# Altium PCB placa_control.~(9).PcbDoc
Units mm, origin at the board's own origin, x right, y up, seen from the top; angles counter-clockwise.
Board outline 152.4 x 101.6 mm, 2 copper layers (Top Layer, Bottom Layer); 35 components, 26 nets, 134 pads, 100 vias.
Unrouted connection lines stored in the file: 44.
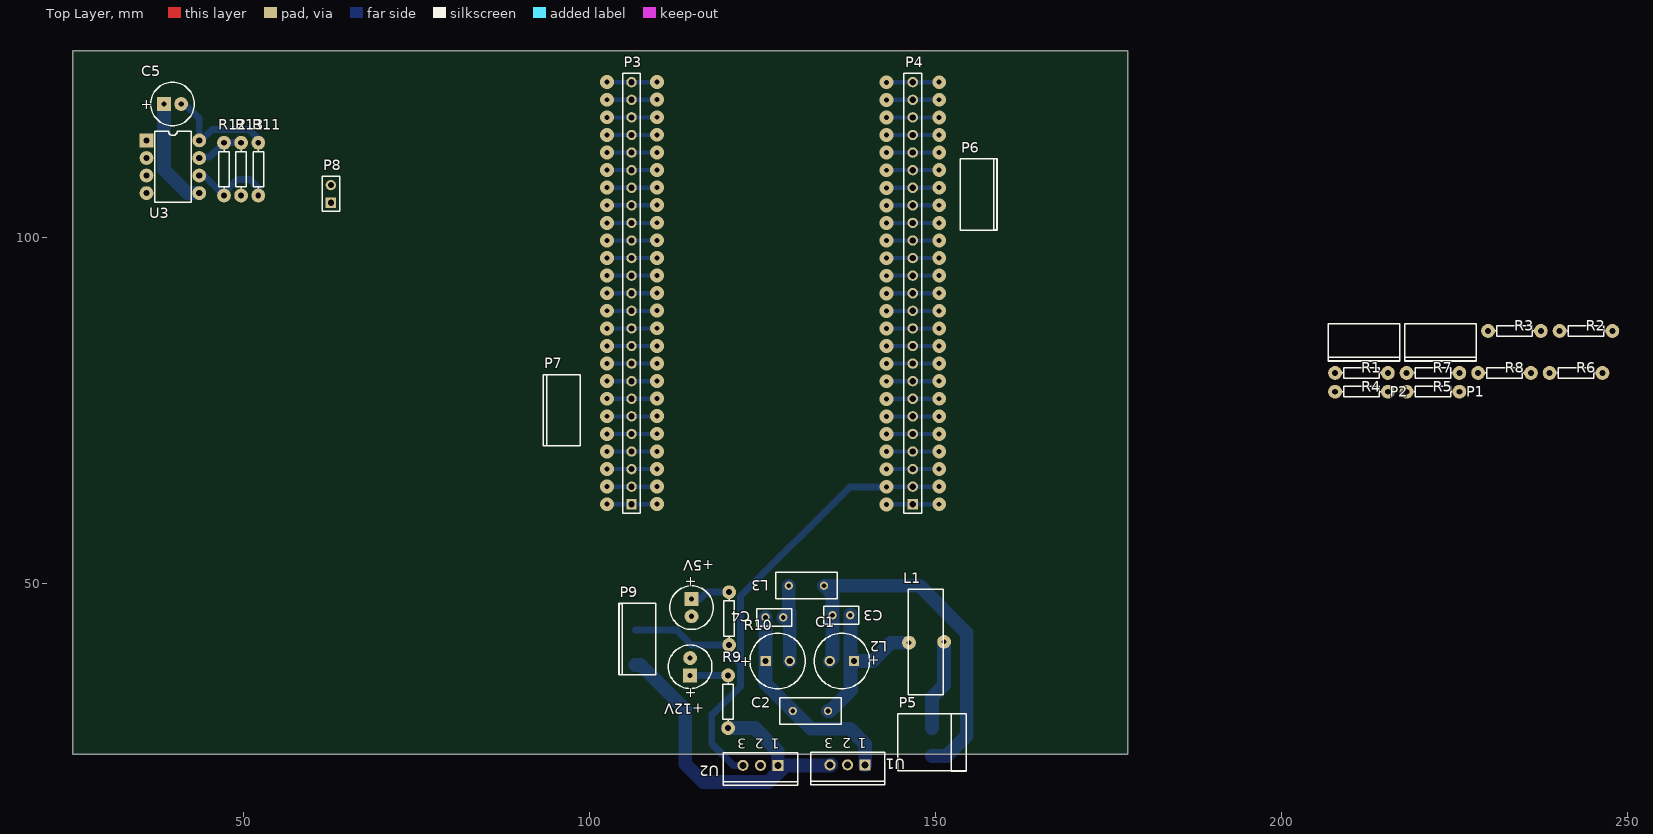
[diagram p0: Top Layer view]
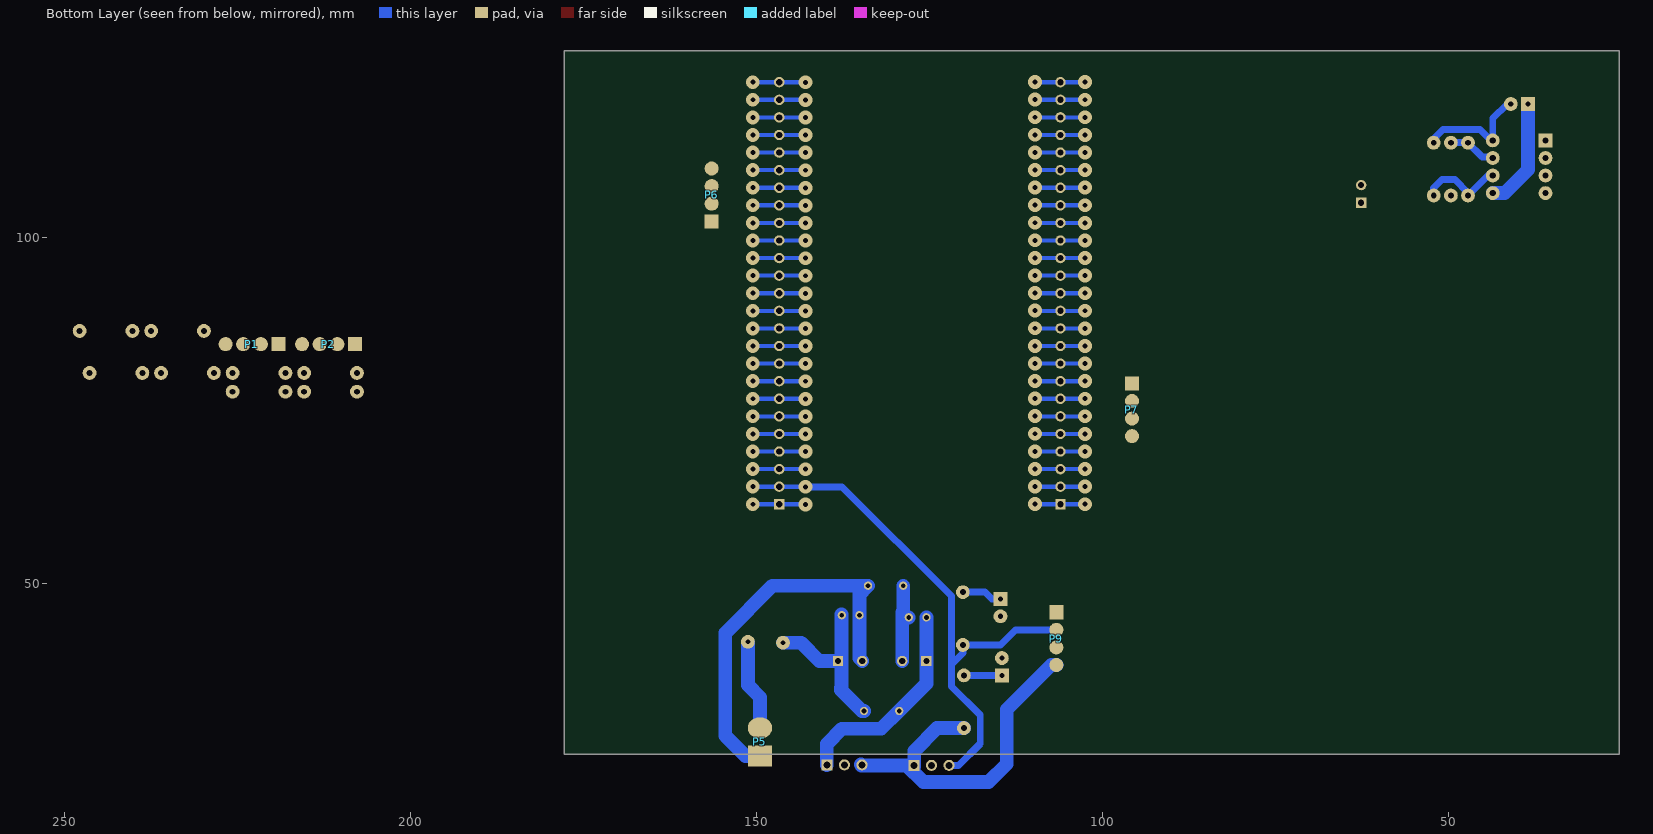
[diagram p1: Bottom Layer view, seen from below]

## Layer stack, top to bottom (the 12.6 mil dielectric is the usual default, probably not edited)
Top Layer: signal copper 0.0356
Dielectric: dielectric 0.32, FR-4, Dk 4.8
Bottom Layer: signal copper 0.0356

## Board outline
25.4,25.4 177.8,25.4 177.8,127 25.4,127

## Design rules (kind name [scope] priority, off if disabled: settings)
Clearance [All] p1: gap=0.254
ComponentClearance [All] p1: gap=0.254 collisioncheckmode=3 verticalgap=0.254
PolygonConnect [All] p1: connectstyle=Relief reliefconductorwidth=0.254 reliefentries=4 polygonreliefangle="90 Angle"
RoomDefinition REGULADOR [InComponentClass('REGULADOR')] p1: confinementstyle=ConfineIn formatcopy=TRUE lockcomponents=FALSE outline 98.375,17.575 155.697,17.575 155.697,54.2 98.375,54.2
RoomDefinition INTERFAZ [InComponentClass('INTERFAZ')] p2: confinementstyle=ConfineIn formatcopy=TRUE lockcomponents=FALSE outline 15.525,100.025 66.325,100.025 66.325,125.425 15.525,125.425
RoomDefinition ENCODER [InComponentClass('ENCODER')] p3: confinementstyle=ConfineIn formatcopy=TRUE lockcomponents=FALSE outline 206.375,62.738 257.175,62.738 257.175,88.138 206.375,88.138
RoomDefinition BOARD-ARM [InComponentClass('BOARD-ARM')] p4: confinementstyle=ConfineOut formatcopy=TRUE lockcomponents=FALSE outline 166.025,120.7 232.827,120.7 232.827,146.1 166.025,146.1
RoomDefinition placa_control_esquema [InComponentClass('placa_control_esquema')] p5: confinementstyle=ConfineIn formatcopy=TRUE lockcomponents=FALSE outline 129.325,143.075 180.125,143.075 180.125,168.475 129.325,168.475
RoutingVias [All] p1: holewidth=0.711 width=2 viastyle="Through Hole" minholewidth=0.711 minwidth=1.27 maxholewidth=0.711 maxwidth=2
SolderMaskExpansion [All] p1: expansion=0.102
TestPointUsage [All] p1: valid=0 allowmultiple=FALSE
Testpoint [All] p1: side=15 testpointundercomponent=TRUE minsize=1.016 maxsize=2.54 preferedsize=1.524 minholesize=0 maxholesize=1.016 preferedholesize=0.813 testpointgrid=0.025 style=1023 order=0123456789
Width [All] p1: maxlimit=2 minlimit=0.6 preferedwidth=0.8
18 further rules are at their usual default settings.

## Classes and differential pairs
component class placa_control_esquema: P6 P7 P9
component class REGULADOR: +5V +12V C1 C2 C3 C4 L1 L2 L3 P5 R9 R10 U1 U2
component class BOARD-ARM: P3 P4
component class ENCODER: P1 P2 R1 R2 R3 R4 R5 R6 R7 R8
component class INTERFAZ: C5 P8 R11 R12 R13 U3

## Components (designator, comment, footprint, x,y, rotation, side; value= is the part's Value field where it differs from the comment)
+5V "LED2" CAPPR2.5-6.3X5 114.783,46.558 r270 top (schematic designator VCC2)
+12V "LED2" CAPPR2.5-6.3X5 114.579,38.024 r90 top (schematic designator VCC1)
C1 "Cap Pol3" CAPPR3.5-8X15 136.495,38.855 r180 top
C2 "Cap Pol3" CAPPR3.5-8X15 127.224,38.855 r0 top
C3 "Cap" RAD-0.1 136.424,45.464 r0 top
C4 "Cap" RAD-0.1 126.747,45.159 r180 top
C5 "Cap" CAPPR2.5-6.3X5 39.819,119.308 r0 top
L1 "Inductor Iron" bobina_Choque 151.137,39.085 r90 top
L2 "Inductor" RAD-0.2 131.949,31.641 r180 top
L3 "Inductor" RAD-0.2 131.369,49.731 r180 top
P1 "Header 4" HDR1X5 226.695,76.989 r0 top
P2 "Header 4" HDR1X5 215.646,76.989 r0 top
P3 "Header 25" HDR1X25 106.115,61.49 r90 top
P4 "Header 25" HDR1X25 146.73,61.49 r90 top
P5 "Header 2" pwheader1x2 149.514,27.285 r90 top
P6 "Header 4" HDR1X5 164.109,109.982 r90 top
P7 "Header 4" HDR1X5 88.163,71.323 r270 top
P8 "Header 2" HDR1X2 62.687,105.054 r90 top
P9 "Header 4" HDR1X5 99.085,38.278 r270 top
R1 "metal film 2%" AXIAL-0.3 211.541,80.459 r0 top
R2 "metal film 2%" AXIAL-0.3 243.97,86.528 r0 top
R3 "metal film 2%" AXIAL-0.3 233.639,86.528 r0 top
R4 "metal film 2%" AXIAL-0.3 211.541,77.748 r0 top
R5 "metal film 2%" AXIAL-0.3 221.872,77.748 r0 top
R6 "metal film 2%" AXIAL-0.3 242.534,80.459 r0 top
R7 "metal film 2%" AXIAL-0.3 221.872,80.459 r0 top
R8 "metal film 2%" AXIAL-0.3 232.203,80.459 r0 top
R9 "Carbon 1/8w 5%" AXIAL-0.3 120.066,32.969 r270 top
R10 "Carbon 1/8w 5%" AXIAL-0.3 120.218,44.983 r270 top
R11 "Carbon 1/8w 5%" AXIAL-0.3 52.204,109.9 r90 top
R12 "Carbon 1/8w 5%" AXIAL-0.3 47.251,109.9 r270 top
R13 "Carbon 1/8w 5%" AXIAL-0.3 49.728,109.9 r90 top
U1 "LM78L12ACZ" T03B 137.32,23.851 r180 top
U2 "LM78L05ACZ" T03B 124.738,23.785 r180 top
U3 "SN75176BP" 626-05 39.869,110.24 r270 top

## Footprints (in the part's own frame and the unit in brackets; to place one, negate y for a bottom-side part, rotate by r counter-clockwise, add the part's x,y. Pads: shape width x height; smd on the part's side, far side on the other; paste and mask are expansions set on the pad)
626-05 [mm] "DIP; 8 Leads; Row Spacing 7.62 mm; Pitch 2.54 mm"
  rect 2x2 hole 0.9: 1(-3.81,-3.81)
  round 2 hole 0.9: 2(-1.27,-3.81) 3(1.27,-3.81) 4(3.81,-3.81) 5(3.81,3.81) 6(1.27,3.81) 7(-1.27,3.81) 8(-3.81,3.81)
  silkscreen extent -5.15,-2.65 5.15,2.65
AXIAL-0.3 [mm] "Resistor; 2 Leads"
  round 2 hole 0.85: 1(-3.81,0) 2(3.81,0)
  silkscreen extent -2.77,-0.76 2.77,0.76
bobina_Choque [mm]
  round 2 hole 0.7: 1(2.54,-0.127) 2(2.413,4.953)
  silkscreen extent -5.08,0 10.16,5.08
CAPPR2.5-6.3X5 [mm] "Capacitor, Electrolytic, Radial; Body 6.3 x 5 mm (Dia.xH typ); Pin Spacing 2.5 mm (typ)"
  rect 2x2 hole 0.75: 1(-1.25,0)
  round 2 hole 0.75: 2(1.25,0)
  silkscreen extent -3.15,-3.15 3.15,3.15
CAPPR3.5-8X15 [mm] "Capacitor, Electrolytic, Radial; Body 8 x 15 mm (Dia.xH typ); Pin Spacing 3.5 mm (typ)"
  rect 1.5x1.5 hole 0.9: 1(-1.75,0)
  round 1.5 hole 0.9: 2(1.75,0)
  silkscreen extent -4,-4 4,4
HDR1X2 [mm] "Connector; Header; 2 Position"
  rect 1.5x1.5 hole 0.9: 1(0,0)
  round 1.5 hole 0.9: 2(2.54,0)
  silkscreen extent -1.27,-1.27 3.81,1.27
HDR1X5 [mil]
  rect 80x80 smd far side: 1(-300,300)
  round 80 smd far side: 2(-200,300) 3(-100,300) 4(0,300)
  silkscreen extent -350,205 55,415
HDR1X25 [mm] "Connector; Header; 25 Position"
  rect 1.5x1.5 hole 0.9: 1(0,0)
  round 1.5 hole 0.9: 2(2.54,0) 3(5.08,0) 4(7.62,0) 5(10.16,0) 6(12.7,0) 7(15.24,0) 8(17.78,0) 9(20.32,0) 10(22.86,0) 11(25.4,0) 12(27.94,0) 13(30.48,0) 14(33.02,0) 15(35.56,0) 16(38.1,0) 17(40.64,0) 18(43.18,0) 19(45.72,0) 20(48.26,0) 21(50.8,0) 22(53.34,0) 23(55.88,0) 24(58.42,0) 25(60.96,0)
  silkscreen extent -1.27,-1.27 62.23,1.27
pwheader1x2 [mm]
  rect 3x3.5 smd far side: 1(-2.159,0)
  oval 3x3.5 smd far side: 2(1.905,0)
  silkscreen extent -4.32,-4.95 3.94,4.95
RAD-0.1 [mm] "Indicating Instrument; 2 Leads"
  round 1.2 hole 0.7: 1(-1.27,0) 2(1.27,0)
  silkscreen extent -2.54,-1.27 2.54,1.27
RAD-0.2 [mm] "Jumper Wire; 2 Leads"
  round 1.2 hole 0.7: 1(-2.54,0) 2(2.54,0)
  silkscreen extent -4.44,-1.91 4.44,1.91
T03B [mm] "TO, Thru-Hole, Vertical, Heatsink Mounted; 3 In-Line Leads; Pitch 2.54 mm"
  rect 1.6x1.6 hole 1: 1(-2.54,0)
  round 1.6 hole 1: 2(0,0) 3(2.54,0)
  silkscreen extent -5.35,-1.85 5.35,2.85

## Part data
+5V +12V: "Typical RED, GREEN, YELLOW, AMBER GaAs LED"
C1: "Polarized Capacitor (Surface Mount)"
C2: "Polarized Capacitor 35V"
C3 C4 C5: "Capacitor"
L1: "Magnetic-Core Inductor"
P1 P2 P6 P7 P9: "Header, 4-Pin"
P3 P4: "Header, 25-Pin"
P5 P8: "Header, 2-Pin"
R1 R2 R3 R4 R5 R6 R7 R8 R9 R10 R11 R12 R13: library part "Res Semi", "Semiconductor Resistor"
U1 U2: "3-Terminal Positive Regulator"
U3: "Differential Bus Transceiver"

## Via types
v1: diameter 2, hole 0.711, Top Layer to Bottom Layer, 100 vias

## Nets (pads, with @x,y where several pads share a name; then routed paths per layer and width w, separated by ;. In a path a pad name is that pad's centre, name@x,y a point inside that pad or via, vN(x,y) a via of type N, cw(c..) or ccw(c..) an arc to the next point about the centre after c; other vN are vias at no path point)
+5V: C5.2 P4.2 P9.2 R10.2 R11.2 U2.3 U3.8 | length 98.7
  Bottom Layer w0.6: v1@143.23,64.03 v1@150.415,64.03
  Bottom Layer w1: C5.2 41.567,119.308 43.679,117.196 U3.8 43.9,114.05 45.5,115.65 50.875,115.65 51.4,115.125 ; 51.387,115.113 52.175,114.325 R11.2@52.175,113.575 ; P9.2 112.592,43.358 114.777,41.173 R10.2 120.218,39.982 121.875,38.325 ; U2.3 120.815,23.785 117.7,26.9 117.7,31.025 121.875,35.2 121.875,48.218 137.672,64.015 v1(142.925,64.015)
  other v1: 150.55,64.035
+12V: P1.1 P2.1 P6.4 P7.4 P9.4 R9.2 U1.3 U2.1 | length 51.7
  Bottom Layer w2: P9.4 107.447,38.278 113.875,31.85 113.875,24 116.5,21.375 125.925,21.375 128.335,23.785 134.832,23.785 U1.3@134.947,23.9 ; R9.2 123.941,29.159 127.225,25.875 U2.1@127.225,23.6
GND: +5V.2 +12V.2 C2.2 C4.1 C5.1 L3.2 P1.2 P2.2 P4.1 P6.3 P7.3 P9.1 P9.3 R2.1 R4.1 R6.1 R8.1 R13.1 U1.2 U2.2 U3.5 | length 35
  Bottom Layer w0.6: v1@143.23,61.49 v1@150.415,61.49
  Bottom Layer w2: C5.1 38.569,109.806 41.945,106.43 U3.5 ; C4.1 128.934,45.159 ; L3.2 128.829,46.032 128.974,45.888 C2.2
  other v1: 142.925,61.475 150.55,61.495
IN_SD_1: P4.21 P6.2 | length 7.2
  Bottom Layer w0.6: v1@143.23,112.29 v1@150.415,112.29
  other v1: 142.925,112.275 150.55,112.295
IN_SD_2: P3.19 P7.2 | length 7.2
  Bottom Layer w0.6: v1@102.615,107.21 v1@109.8,107.21
  other v1: 102.575,107.22 109.775,107.235
NetC1_1: C1.1 C3.2 L1.2 L2.1 | length 29.3
  Bottom Layer w2: L2.1 134.788,31.641 137.797,34.65 137.797,34.95 137.747,35 C3.2@137.747,45.575 ; 137.694,40.65 C3.2 ; C1.1 140.952,38.855 143.595,41.498 L1.2
NetC1_2: C1.2 C3.1 L3.1 P5.1 | length 56.1
  Bottom Layer w2: C1.2 135.154,39.264 135.154,48.487 L3.1 147.716,49.731 154.522,42.925 154.522,28.05 151.598,25.126 P5.1
NetC2_1: C2.1 C4.2 L2.2 U1.1 | length 30.6
  Bottom Layer w2: C4.2 125.477,35.573 L2.2 129.431,31.641 131.997,29.075 137.672,29.075 139.86,26.887 U1.1
NetL1_1: L1.1 P5.2 | length 13.2
  Bottom Layer w0.6: L1.1@151.264,41.467 L1.1
  Bottom Layer w2: P5.2 149.514,33.617 151.264,35.367 L1.1@151.264,41.467
NetP1_3: P1.3 R1.2
NetP1_4: P1.4 R3.2
NetP2_3: P2.3 R5.2
NetP2_4: P2.4 R7.2
NetP3_6: P3.6 U3.2 U3.3 | length 7.2
  Bottom Layer w0.6: v1@102.615,74.19 v1@109.8,74.19
  other v1: 102.575,74.2 109.775,74.215
NetP3_7: P3.7 U3.1 | length 7.2
  Bottom Layer w0.6: v1@102.615,76.73 v1@109.8,76.73
  other v1: 102.575,76.74 109.775,76.755
NetP3_8: P3.8 U3.4 | length 7.2
  Bottom Layer w0.6: v1@102.615,79.27 v1@109.8,79.27
  other v1: 102.575,79.28 109.775,79.295
NetP3_20: P3.20 R7.1 R8.2 | length 7.2
  Bottom Layer w0.6: v1@102.615,109.75 v1@109.8,109.75
  other v1: 102.575,109.76 109.775,109.775
NetP3_21: P3.21 R5.1 R6.2 | length 7.2
  Bottom Layer w0.6: v1@102.615,112.29 v1@109.8,112.29
  other v1: 102.575,112.3 109.775,112.315
NetP4_14: P4.14 R3.1 R4.2 | length 7.2
  Bottom Layer w0.6: v1@143.23,94.51 v1@150.415,94.51
  other v1: 142.925,94.495 150.55,94.515
NetP4_15: P4.15 R1.1 R2.2 | length 7.2
  Bottom Layer w0.6: v1@143.23,97.05 v1@150.415,97.05
  other v1: 142.925,97.035 150.55,97.055
NetP8_1: P8.1 R11.1 R12.2 U3.6 | length 12.5
  Bottom Layer w1: U3.6 44.371,108.97 R12.2 47.251,106.476 49.15,108.375 51,108.375 52.204,107.171 R11.1
NetP8_2: P8.2 R12.1 R13.2 U3.7 | length 7
  Bottom Layer w1: U3.7@43.725,111.65 45.191,111.65 47.291,113.75 R13.2@49.825,113.75
NetR9_1: +12V.1 R9.1 | length 5.5
  Bottom Layer w1: +12V.1 R9.1@120.124,36.774
NetR10_1: +5V.1 R10.1 | length 5.8
  Bottom Layer w1: +5V.1 116.033,47.808 117.018,48.793 R10.1
PWM_1: P4.16 P6.1 | length 7.2
  Bottom Layer w0.6: v1@143.23,99.59 v1@150.415,99.59
  other v1: 142.925,99.575 150.55,99.595
PWM_2: P3.9 P7.1 | length 7.2
  Bottom Layer w0.6: v1@102.615,81.81 v1@109.8,81.81
  other v1: 102.575,81.82 109.775,81.835
pads on no net: P3.1 P3.2 P3.3 P3.4 P3.5 P3.10 P3.11 P3.12 P3.13 P3.14 P3.15 P3.16 P3.17 P3.18 P3.22 P3.23 P3.24 P3.25 P4.3 P4.4 P4.5 P4.6 P4.7 P4.8 P4.9 P4.10 P4.11 P4.12 P4.13 P4.17 P4.18 P4.19 P4.20 P4.22 P4.23 P4.24 P4.25
copper on no net: | length 265.8
  Bottom Layer w0.6: v1@102.615,61.49 v1@109.8,61.49 ; v1@102.615,64.03 v1@109.8,64.03 ; v1@102.615,66.57 v1@109.8,66.57 ; v1@102.615,69.11 v1@109.8,69.11 ; v1@102.615,71.65 v1@109.8,71.65 ; v1@102.615,84.35 v1@109.8,84.35 ; v1@102.615,86.89 v1@109.8,86.89 ; v1@102.615,89.43 v1@109.8,89.43 ; v1@102.615,91.97 v1@109.8,91.97 ; v1@102.615,94.51 v1@109.8,94.51 ; v1@102.615,97.05 v1@109.8,97.05 ; v1@102.615,99.59 v1@109.8,99.59 ; v1@102.615,102.13 v1@109.8,102.13 ; v1@102.615,104.67 v1@109.8,104.67 ; v1@102.615,114.83 v1@109.8,114.83 ; v1@102.615,117.37 v1@109.8,117.37 ; v1@102.615,119.91 v1@109.8,119.91 ; v1@102.615,122.45 v1@109.8,122.45 ; v1@143.23,66.57 v1@150.415,66.57 ; v1@143.23,69.11 v1@150.415,69.11 ; v1@143.23,71.65 v1@150.415,71.65 ; v1@143.23,74.19 v1@150.415,74.19 ; v1@143.23,76.73 v1@150.415,76.73 ; v1@143.23,79.27 v1@150.415,79.27 ; v1@143.23,81.81 v1@150.415,81.81 ; v1@143.23,84.35 v1@150.415,84.35 ; v1@143.23,86.89 v1@150.415,86.89 ; v1@143.23,89.43 v1@150.415,89.43 ; v1@143.23,91.97 v1@150.415,91.97 ; v1@143.23,102.13 v1@150.415,102.13 ; v1@143.23,104.67 v1@150.415,104.67 ; v1@143.23,107.21 v1@150.415,107.21 ; v1@143.23,109.75 v1@150.415,109.75 ; v1@143.23,114.83 v1@150.415,114.83 ; v1@143.23,117.37 v1@150.415,117.37 ; v1@143.23,119.91 v1@150.415,119.91 ; v1@143.23,122.45 v1@150.415,122.45
  other v1: 102.575,61.5 109.775,61.515 102.575,64.04 109.775,64.055 142.925,66.555 102.575,66.58 150.55,66.575 109.775,66.595 142.925,69.095 102.575,69.12 150.55,69.115 109.775,69.135 142.925,71.635 102.575,71.66 150.55,71.655 109.775,71.675 142.925,74.175 150.55,74.195 142.925,76.715 150.55,76.735 142.925,79.255 150.55,79.275 142.925,81.795 150.55,81.815 142.925,84.335 102.575,84.36 150.55,84.355 109.775,84.375 142.925,86.875 102.575,86.9 150.55,86.895 109.775,86.915 142.925,89.415 102.575,89.44 150.55,89.435 109.775,89.455 142.925,91.955 102.575,91.98 150.55,91.975 109.775,91.995 102.575,94.52 109.775,94.535 102.575,97.06 109.775,97.075 102.575,99.6 109.775,99.615 142.925,102.115 102.575,102.14 150.55,102.135 109.775,102.155 142.925,104.655 102.575,104.68 150.55,104.675 109.775,104.695 142.925,107.195 150.55,107.215 142.925,109.735 150.55,109.755 142.925,114.815 102.575,114.84 150.55,114.835 109.775,114.855 142.925,117.355 102.575,117.38 150.55,117.375 109.775,117.395 142.925,119.895 102.575,119.92 150.55,119.915 109.775,119.935 142.925,122.435 102.575,122.46 150.55,122.455 109.775,122.475

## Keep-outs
Drill Drawing:
  rectangle: 103.875,54.5 149.275,124.7

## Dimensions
149.85,129.875 to 109.25,128.65 on Top Layer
